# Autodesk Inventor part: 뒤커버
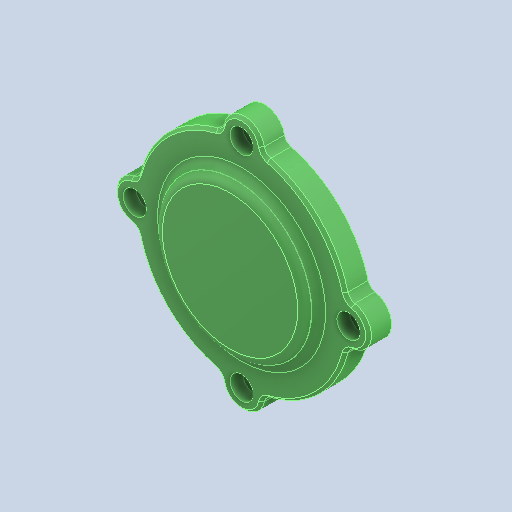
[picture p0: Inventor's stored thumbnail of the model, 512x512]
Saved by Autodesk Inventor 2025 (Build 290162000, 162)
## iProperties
Created: 2024-08
Part Number: 뒤커버
Material: 알루미늄 6061
Document SubType Name: Modeling
Designer: hsj03
Density: 2.71 g/cm^3
Appearance: 기본값
Company: 한국ATC센터
Author: jhkim
Sending System: Autodesk Inventor 2025
Preprocessor: ST-DEVELOPER v20
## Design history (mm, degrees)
feature "솔리드1"
node "솔리드2"
